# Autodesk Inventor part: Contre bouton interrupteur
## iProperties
Created: 2002-05
Part Number: Contre bouton interrupteur
Material: Par défaut
Document SubType Name: Modélisation
Designer: Flavien MARTY
Control State: 0
Master: False
Checked Out: False
Shininess: 20.0
Length Units: 11269
Angle Units: 11279
Time Units: 11290
Mass Units: 11283
Length Display Precision: 3
Angle Display Precision: 2
Compacted: True
Density: 0.0
Volumn: 0.0
Area: 0.0
PropertySet Name: Model Information
Author: Flavien MARTY
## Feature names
1. Extrusion1
2. Extrusion2
3. Extrusion3
4. Congé1 [Fillet]
